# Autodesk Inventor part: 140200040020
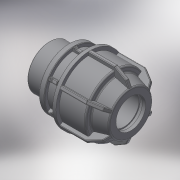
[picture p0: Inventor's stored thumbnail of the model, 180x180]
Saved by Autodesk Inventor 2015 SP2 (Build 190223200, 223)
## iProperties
Created: 2017-08
Part Number: 140200040020
Material: Generic
Description: PLASSON L.14 MALE ADAPTOR (SILVER) 40-2''
Document SubType Name: Modeling
Designer: KIM
Density: 1 g/cm^3
Appearance: Default
Author: KIM
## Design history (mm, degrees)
derived "140200.ipt"
feature "Solid1::140200.ipt"
tag "TaggingFeature1"
body "Solid1"
other parameters: "d4" = 15 deg, "d5" = 59.4, "d6" = 19.602, "d10" = 92, "d16" = 40.8, "d17" = 4.5, "d19" = 7.8, "d21" = 7.8, "d22" = 71.5368, "d24" = 4.5, "d25" = 82.8, "d26" = 69, "d27" = 4.5, "d28" = 135 deg, "d29" = 2.7, "d31" = 2, "d44" = 0.8, "d45" = 1.2, "d46" = 150 deg, "d49" = 4.6, "d50" = 0, "d51" = 0.92, "d52" = 1.84, "d53" = 45 deg, "d54" = 21, "d55" = 6.3, "d56" = 4.6, "d57" = 0, "d58" = 1.2, "d59" = 0.8, "d61" = 360 deg, "d63" = 59.614, "d64" = 32, "d65" = 26, "d66" = 80.4789, "R_" = 59.614, "E_" = 92, "l_2" = 26
